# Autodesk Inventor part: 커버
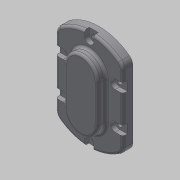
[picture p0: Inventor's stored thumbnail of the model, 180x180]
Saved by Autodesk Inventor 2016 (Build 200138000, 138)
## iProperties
Created: 2019-03
Part Number: 커버
Material: 알루미늄 6061
Document SubType Name: Modeling
Designer: mduedu
Density: 1 g/cm^3
Appearance: 기본값
Author: mduedu
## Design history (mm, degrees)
sketch "스케치1"
  geometry: L1 (44.721, -40)-(-44.721, -40); L2 (44.721, 40)-(-44.721, 40); A1 r 60 centre (0, 0) between (44.721, -40) and (44.721, 40); A2 r 60 centre (0, 0) between (-44.721, 40) and (-44.721, -40); 5 further points
  constraints: 6 point on circle, 4 end point, 2 centre point, 2 coincident, 2 horizontal alignment, 2 midpoint, 2 vertical alignment, 1 horizontal, 1 parallel
  dimensions: "d0" = 60 radius of A1; "d2" = 80 distance between parallel lines of L2 L1; "d3" = 120 distance of point (-60, 0) point (60, 0) (derived)
extrude "돌출1" new body sketch "스케치1" distance "d4" = 12; taper "d5" = 0 deg
sketch "스케치2"
  geometry: L1 (-20, -22)-(20, -22); L2 (20, -22)-(20, 22); L3 (20, 22)-(-20, 22); L4 (-20, 22)-(-20, -22); L5 (-20, -22)-(20, 22); L6 (20, -22)-(-20, 22); 3 further points
  constraints: 12 end point, 4 midpoint, 2 horizontal alignment, 2 parallel, 1 horizontal, 1 perpendicular, 4 other
  dimensions: "d6" = 40 distance between parallel lines of L2 L4; "d8" = 44 distance between parallel lines of L1 L3
extrude "돌출2" join sketch "스케치2" distance "d9" = 10; taper "d10" = 0 deg
fillet "모깎기1" dims "d11" = 10
fillet "모깎기2" dims "d12" = 3
sketch "스케치3"
  geometry: L1 (31, -22)-(31, 22); L2 (-31, 22)-(-31, -22); L3 (-31, -22)-(31, 22); L4 (31, -22)-(-31, 22); A1 r 31 centre (0, 22) between (31, 22) and (-31, 22); A2 r 31 centre (0, -22) between (-31, -22) and (31, -22); 7 further points
  constraints: 8 end point, 6 point on circle, 4 coincident, 3 tangent, 2 centre point, 2 midpoint, 1 parallel, 1 vertical, 1 vertical alignment
  dimensions: "d13" = 31 radius of A1; "d15" = 44 distance of A2.centre A1.centre
hole "구멍2" sketch "스케치3" at (-31, 22), (-31, -22), (31, -22), (31, 22), (0, 53), (0, -53) diameter "d28" = 5.5; stored, may be unused: countersink angle "d32" = 90 deg, drill point angle "d34" = 118 deg; dims "d29" = 6, "d30" = 4, "d31" = 2, "d33" = 8
sketch "스케치5"
  geometry: L1 (-40, 40)-(-40, -40) reference; L2 (40, -40)-(40, 40) reference; L3 (-5.5, 53)-(-5.5, 59.747); L4 (5.5, 53)-(5.5, 59.747); L5 (-31, 27.5)-(-40, 27.5); L6 (-31, 16.5)-(-40, 16.5); L7 (-31, -16.5)-(-40, -16.5); L8 (-31, -27.5)-(-40, -27.5); L9 (-5.5, -53)-(-5.5, -59.747); L10 (5.5, -53)-(5.5, -59.747); L11 (31, -27.5)-(40, -27.5); L12 (31, -16.5)-(40, -16.5); L13 (31, 16.5)-(40, 16.5); L14 (31, 27.5)-(40, 27.5); C1 r 2.75 at (0, 53) reference; C2 r 2.75 at (-31, 22) reference; C3 r 2.75 at (-31, -22) reference; C4 r 2.75 at (0, -53) reference; C5 r 2.75 at (31, -22) reference; C6 r 2.75 at (31, 22) reference; A1 r 60 centre (0, 0) between (36, 48) and (-36, 48) reference; A2 r 10 centre (-30, 40) between (-36, 48) and (-40, 40) reference; A3 r 10 centre (-30, -40) between (-40, -40) and (-36, -48) reference; A4 r 60 centre (0, 0) between (-36, -48) and (36, -48) reference; A5 r 10 centre (30, -40) between (36, -48) and (40, -40) reference; A6 r 10 centre (30, 40) between (40, 40) and (36, 48) reference; A7 r 5.5 centre (0, 53) between (-5.5, 53) and (5.5, 53); A8 r 5.5 centre (-31, 22) between (-31, 16.5) and (-31, 27.5); A9 r 5.5 centre (-31, -22) between (-31, -27.5) and (-31, -16.5); A10 r 5.5 centre (0, -53) between (5.5, -53) and (-5.5, -53); A11 r 5.5 centre (31, -22) between (31, -16.5) and (31, -27.5); A12 r 5.5 centre (31, 22) between (31, 27.5) and (31, 16.5); 1 further point
  constraints: 24 end point, 16 point on circle, 12 tangent, 8 parallel, 8 point on line, 6 centre point, 5 concentric, 4 horizontal, 1 coincident, 1 vertical
  dimensions: "d35" = 11 diameter of A7; "d36" = 11 diameter of A8; "d37" = 11 diameter of A9; "d38" = 11 diameter of A10; "d39" = 11 diameter of A11; "d40" = 11 diameter of A12
extrude "돌출4" cut sketch "스케치5" distance "d41" = 5.4; taper "d42" = 0 deg
sketch "스케치6"
  geometry: C1 r 12.5 at (0, 22); 1 further point
  constraints: 1 centre point, 1 vertical alignment
  dimensions: "d43" = 25 diameter of C1; "d45" = 22 distance of C1.centre point (0, 0)
extrude "돌출5" cut sketch "스케치6" distance "d47" = 15; taper "d48" = 0 deg
node "솔리드1"
mirror "대칭1"
